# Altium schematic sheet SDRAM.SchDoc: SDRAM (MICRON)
size A4; Date: 25-FEB-2015; Author: A.B; CompanyName: STMicroelectronics; Address1: 12, Rue Jules HOROWITZ; Address2: 38019 Grenoble; Address3: FRANCE; DocumentNumber: MB1191; Revision: B-02; SheetNumber: 7; SheetTotal: 13; Project: STM32F746G-DISCO
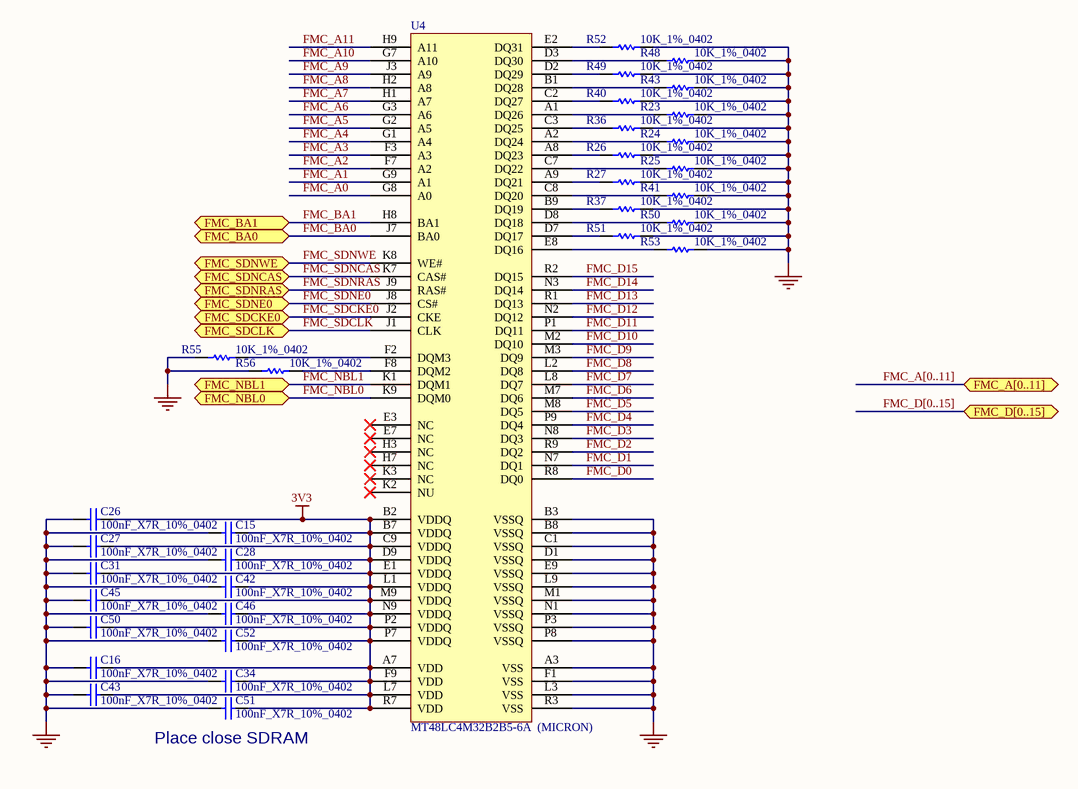
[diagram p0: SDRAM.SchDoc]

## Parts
C15  100nF_X7R_10%_0402  [0402C]
C16  100nF_X7R_10%_0402  [0402C]
C26  100nF_X7R_10%_0402  [0402C]
C27  100nF_X7R_10%_0402  [0402C]
C28  100nF_X7R_10%_0402  [0402C]
C31  100nF_X7R_10%_0402  [0402C]
C34  100nF_X7R_10%_0402  [0402C]
C42  100nF_X7R_10%_0402  [0402C]
C43  100nF_X7R_10%_0402  [0402C]
C45  100nF_X7R_10%_0402  [0402C]
C46  100nF_X7R_10%_0402  [0402C]
C50  100nF_X7R_10%_0402  [0402C]
C51  100nF_X7R_10%_0402  [0402C]
C52  100nF_X7R_10%_0402  [0402C]
R23  10K_1%_0402  [0402R]
R24  10K_1%_0402  [0402R]
R25  10K_1%_0402  [0402R]
R26  10K_1%_0402  [0402R]
R27  10K_1%_0402  [0402R]
R36  10K_1%_0402  [0402R]
R37  10K_1%_0402  [0402R]
R40  10K_1%_0402  [0402R]
R41  10K_1%_0402  [0402R]
R43  10K_1%_0402  [0402R]
R48  10K_1%_0402  [0402R]
R49  10K_1%_0402  [0402R]
R50  10K_1%_0402  [0402R]
R51  10K_1%_0402  [0402R]
R52  10K_1%_0402  [0402R]
R53  10K_1%_0402  [0402R]
R55  10K_1%_0402  [0402R]
R56  10K_1%_0402  [0402R]
U4  MT48LC4M32B2B5-6A  (MICRON)  [FBGA90_0R8_8X13]

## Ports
FMC_A[0..11], FMC_BA0, FMC_BA1, FMC_D[0..15], FMC_NBL0, FMC_NBL1, FMC_SDCKE0, FMC_SDCLK, FMC_SDNCAS, FMC_SDNE0, FMC_SDNRAS, FMC_SDNWE

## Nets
3V3: C15.2 C16.2 C26.2 C27.2 C28.2 C31.2 C34.2 C42.2 C43.2 C45.2 C46.2 C50.2 C51.2 C52.2 U4.A7(VDD) U4.B2(VDDQ) U4.B7(VDDQ) U4.C9(VDDQ) U4.D9(VDDQ) U4.E1(VDDQ) U4.F9(VDD) U4.L1(VDDQ) U4.L7(VDD) U4.M9(VDDQ) U4.N9(VDDQ) U4.P2(VDDQ) U4.P7(VDDQ) U4.R7(VDD)
GND: C15.1 C16.1 C26.1 C27.1 C28.1 C31.1 C34.1 C42.1 C43.1 C45.1 C46.1 C50.1 C51.1 C52.1 R23.2 R24.2 R25.2 R26.2 R27.2 R36.2 R37.2 R40.2 R41.2 R43.2 R48.2 R49.2 R50.2 R51.2 R52.2 R53.2 R55.1 R56.1 U4.A3(VSS) U4.B3(VSSQ) U4.B8(VSSQ) U4.C1(VSSQ) U4.D1(VSSQ) U4.E9(VSSQ) U4.F1(VSS) U4.L3(VSS) U4.L9(VSSQ) U4.M1(VSSQ) U4.N1(VSSQ) U4.P3(VSSQ) U4.P8(VSSQ) U4.R3(VSS)
FMC_A0: U4.G8(A0)
FMC_A1: U4.G9(A1)
FMC_A2: U4.F7(A2)
FMC_A3: U4.F3(A3)
FMC_A4: U4.G1(A4)
FMC_A5: U4.G2(A5)
FMC_A6: U4.G3(A6)
FMC_A7: U4.H1(A7)
FMC_A8: U4.H2(A8)
FMC_A9: U4.J3(A9)
FMC_A10: U4.G7(A10)
FMC_A11: U4.H9(A11)
FMC_BA0: U4.J7(BA0) ; port FMC_BA0
FMC_BA1: U4.H8(BA1) ; port FMC_BA1
FMC_D0: U4.R8(DQ0)
FMC_D1: U4.N7(DQ1)
FMC_D2: U4.R9(DQ2)
FMC_D3: U4.N8(DQ3)
FMC_D4: U4.P9(DQ4)
FMC_D5: U4.M8(DQ5)
FMC_D6: U4.M7(DQ6)
FMC_D7: U4.L8(DQ7)
FMC_D8: U4.L2(DQ8)
FMC_D9: U4.M3(DQ9)
FMC_D10: U4.M2(DQ10)
FMC_D11: U4.P1(DQ11)
FMC_D12: U4.N2(DQ12)
FMC_D13: U4.R1(DQ13)
FMC_D14: U4.N3(DQ14)
FMC_D15: U4.R2(DQ15)
FMC_NBL0: U4.K9(DQM0) ; port FMC_NBL0
FMC_NBL1: U4.K1(DQM1) ; port FMC_NBL1
FMC_SDCKE0: U4.J2(CKE) ; port FMC_SDCKE0
FMC_SDCLK: U4.J1(CLK) ; port FMC_SDCLK
FMC_SDNCAS: U4.K7(CAS#) ; port FMC_SDNCAS
FMC_SDNE0: U4.J8(CS#) ; port FMC_SDNE0
FMC_SDNRAS: U4.J9(RAS#) ; port FMC_SDNRAS
FMC_SDNWE: U4.K8(WE#) ; port FMC_SDNWE
NetR23_1: R23.1 U4.A1(DQ26)
NetR24_1: R24.1 U4.A2(DQ24)
NetR25_1: R25.1 U4.C7(DQ22)
NetR26_1: R26.1 U4.A8(DQ23)
NetR27_1: R27.1 U4.A9(DQ21)
NetR36_1: R36.1 U4.C3(DQ25)
NetR37_1: R37.1 U4.B9(DQ19)
NetR40_1: R40.1 U4.C2(DQ27)
NetR41_1: R41.1 U4.C8(DQ20)
NetR43_1: R43.1 U4.B1(DQ28)
NetR48_1: R48.1 U4.D3(DQ30)
NetR49_1: R49.1 U4.D2(DQ29)
NetR50_1: R50.1 U4.D8(DQ18)
NetR51_1: R51.1 U4.D7(DQ17)
NetR52_1: R52.1 U4.E2(DQ31)
NetR53_1: R53.1 U4.E8(DQ16)
NetR55_2: R55.2 U4.F2(DQM3)
NetR56_2: R56.2 U4.F8(DQM2)

Not connected (* = marked no-connect by the designer): U4 E3(NC)* E7(NC)* H3(NC)* H7(NC)* K2(NU)* K3(NC)*

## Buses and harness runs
bus FMC_A[0..11] = port FMC_A[0..11]
bus FMC_D[0..15] = port FMC_D[0..15]

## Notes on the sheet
- (near C51) Place close SDRAM

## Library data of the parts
C15 C16 C26-C28 C31 C34 C42 C43 C45 C46 C50-C52 = Cap_100nF_X7R_10%_0402: Capacitor,100nF,16V,X7R,10%,0402,YAGEO; Manuf_Part_1: CC0402KRX7R7BB104
R23-R27 R36 R37 R40 R41 R43 R48-R53 R55 R56 = Res_10K_1%_0402: Resistor,10K,0402,1%,YAGEO; Manuf_Part_1: RC0402FR-0710KL
U4 = MT48LC4M32B2B5-6A: SDRAM 128MBIT (4M x 32) 166MHZ 90-VFBGA (8x13); Manuf_Part_1: MT48LC4M32B2B5-6A IT:L TR; Order: MT48LC4M32B2B5-6A IT:L TR-ND; ECCN_US/EU: EAR99/NEC; Provided: ST; Ref St: 9171434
